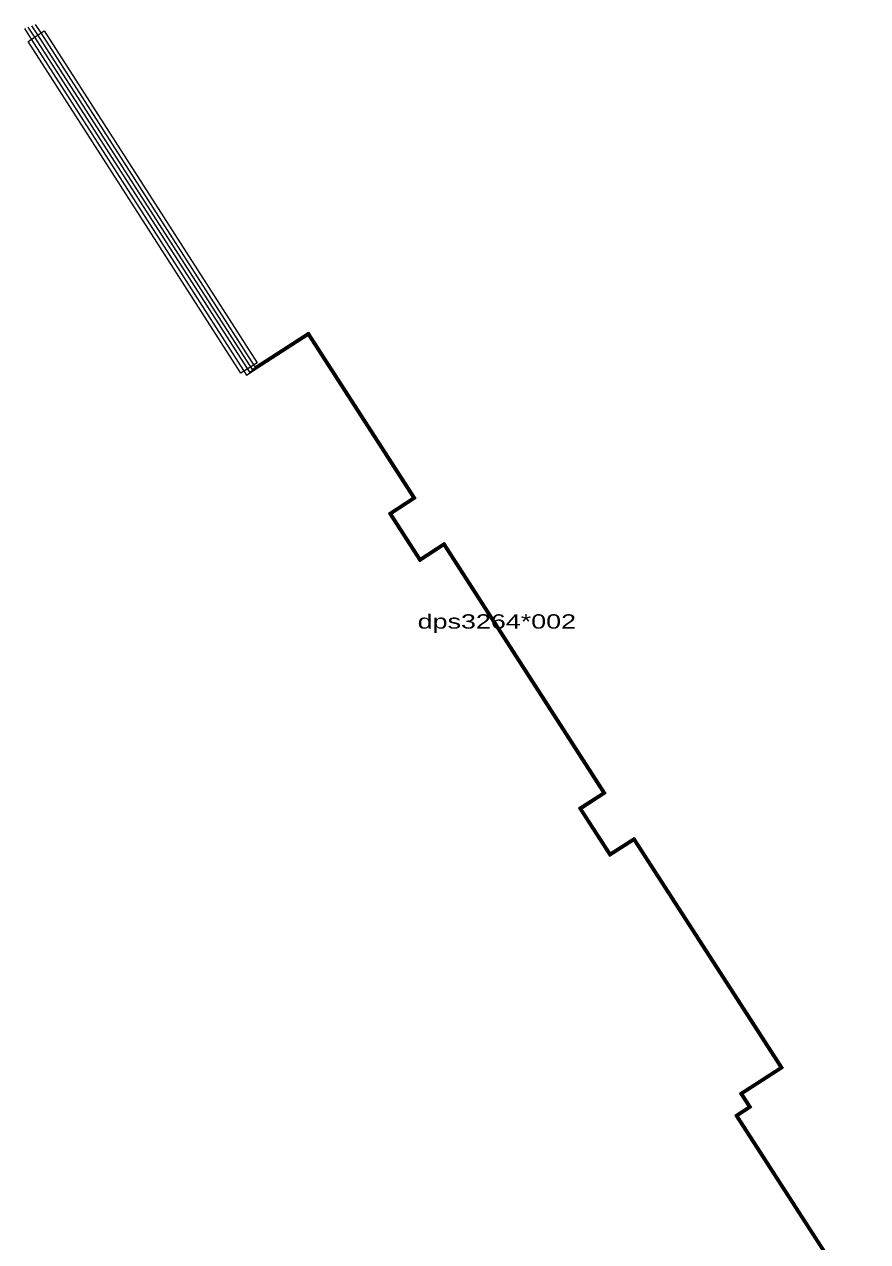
# Model space of a CAD drawing. Extents: x -473467 to -473049, y -1106745 to -1106181.
# Drawn here: x -473291.5 to -473238.6, y -1106257.8 to -1106181.5 of the extents above; entities that cross this region are included whole.
import ezdxf
from ezdxf.enums import TextEntityAlignment as Align

# ---------------------------------------------------------------- set-up
doc = ezdxf.new("R2010")
doc.units = 0
doc.header["$LTSCALE"] = 0.36
doc.layers.add('11', color=7, linetype='Continuous', lineweight=13)
doc.layers.add('17', color=7, linetype='Continuous', lineweight=13)
doc.layers.add('19', color=7, linetype='Continuous')

msp = doc.modelspace()

# ---------------------------------------------------------------- linework, layer by layer
at = {"layer": '11'}
for points in [[(-473291.256, -1106181.66), (-473290.857, -1106182.283), (-473277.368, -1106203.303)], [(-473291.027, -1106181.572), (-473290.655, -1106182.153), (-473277.194, -1106203.132)], [(-473290.798, -1106181.485), (-473290.453, -1106182.024), (-473277.019, -1106202.959)], [(-473291.485, -1106181.747), (-473291.059, -1106182.412), (-473277.543, -1106203.475)], [(-473277.019, -1106202.959), (-473273.658, -1106200.792), (-473266.928, -1106211.226), (-473268.441, -1106212.202), (-473266.663, -1106214.958), (-473265.151, -1106213.983), (-473255.005, -1106229.715), (-473256.517, -1106230.691), (-473254.74, -1106233.447), (-473253.227, -1106232.471), (-473243.894, -1106246.943), (-473246.415, -1106248.569), (-473245.873, -1106249.409), (-473246.714, -1106249.951), (-473240.235, -1106259.997), (-473238.589, -1106262.55)], [(-473277.543, -1106203.475), (-473276.937, -1106203.085), (-473273.703, -1106200.999), (-473267.136, -1106211.182), (-473268.648, -1106212.157), (-473266.708, -1106215.166), (-473265.195, -1106214.19), (-473255.212, -1106229.67), (-473256.725, -1106230.646), (-473254.784, -1106233.654), (-473253.272, -1106232.679), (-473244.101, -1106246.898), (-473246.623, -1106248.524), (-473246.081, -1106249.365), (-473246.921, -1106249.907), (-473240.361, -1106260.078), (-473238.707, -1106262.643)], [(-473277.368, -1106203.303), (-473276.964, -1106203.043), (-473273.688, -1106200.93), (-473267.067, -1106211.197), (-473268.579, -1106212.172), (-473266.693, -1106215.097), (-473265.18, -1106214.121), (-473255.143, -1106229.685), (-473256.656, -1106230.661), (-473254.77, -1106233.585), (-473253.257, -1106232.61), (-473244.032, -1106246.913), (-473246.553, -1106248.539), (-473246.011, -1106249.379), (-473246.852, -1106249.921), (-473240.319, -1106260.051), (-473238.667, -1106262.612)], [(-473277.194, -1106203.132), (-473273.673, -1106200.861), (-473266.997, -1106211.211), (-473268.51, -1106212.187), (-473266.678, -1106215.028), (-473265.166, -1106214.052), (-473255.074, -1106229.7), (-473256.587, -1106230.676), (-473254.755, -1106233.516), (-473253.242, -1106232.541), (-473243.963, -1106246.928), (-473246.484, -1106248.554), (-473245.942, -1106249.394), (-473246.783, -1106249.936), (-473240.277, -1106260.024), (-473238.628, -1106262.581)]]:
    msp.add_lwpolyline(points, dxfattribs=at)
at = {"layer": '17'}
msp.add_lwpolyline([(-473291.253, -1106182.554), (-473290.251, -1106181.894), (-473276.887, -1106202.72), (-473277.897, -1106203.368)], close=True, dxfattribs=at)

# ---------------------------------------------------------------- texts
at = {"layer": '19', "width": 1.4}
msp.add_text('dps3264*002', height=0.9, dxfattribs=at).set_placement((-473261.848, -1106219.38), align=Align.CENTER)

doc.saveas('drawing.dxf')
